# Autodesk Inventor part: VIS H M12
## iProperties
Created: 2004-11
Part Number: VIS H M12
Document SubType Name: Modeling
Designer: Bruno
Manufacturer: Standard
Standards Organization: Custom
Author: Bruno
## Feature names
1. Base1
